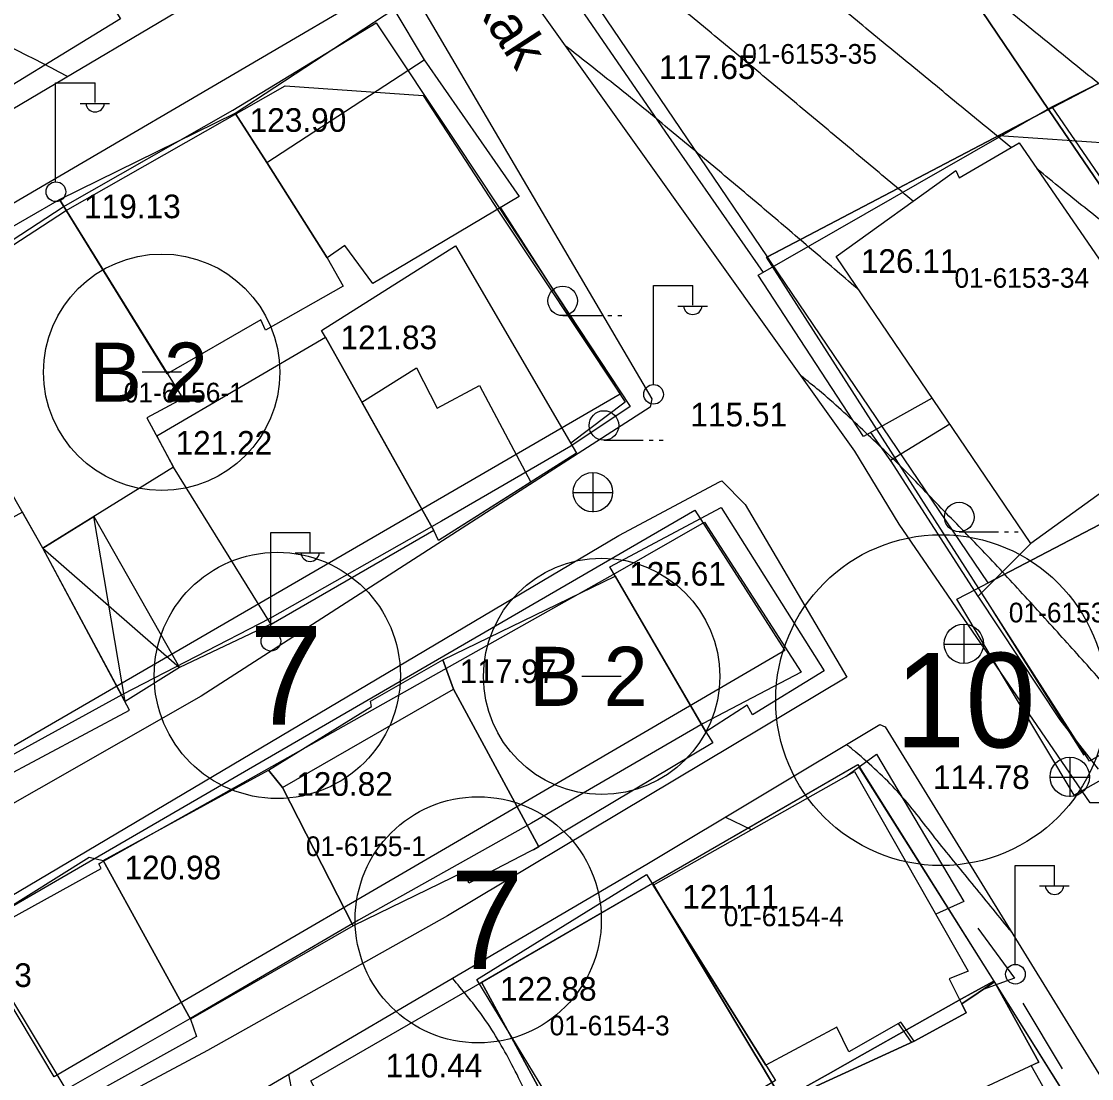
# Model space of a CAD drawing. Extents: x 412225 to 413380, y 4456471 to 4457189.
# Drawn here: x 413052.1 to 413106.4, y 4456895.9 to 4456949.5 of the extents above; entities that cross this region are included whole.
import ezdxf

# ---------------------------------------------------------------- set-up
doc = ezdxf.new("R2010")
doc.units = 0
for name, color, linetype in [('0_HALİHAZIR', 7, 'Continuous'), ('0_KADASTRO', 7, 'Continuous'), ('Level 27', 7, 'Continuous'), ('Level 28', 7, 'Continuous'), ('Level 32', 7, 'Continuous'), ('Level 58', 7, 'Continuous')]:
    doc.layers.add(name, color=color, linetype=linetype)

msp = doc.modelspace()

# ---------------------------------------------------------------- linework, layer by layer
at = {"layer": '0_HALİHAZIR'}
for p, q in [((413053.795, 4456941.409), (413053.795, 4456946.409)), ((413053.795, 4456946.409), (413055.795, 4456946.409)), ((413055.795, 4456945.409), (413055.795, 4456946.409)), ((413055.035, 4456945.369), (413056.535, 4456945.369)), ((413084.144, 4456931.12), (413084.144, 4456936.12)), ((413084.144, 4456936.12), (413086.144, 4456936.12)), ((413086.144, 4456935.12), (413086.144, 4456936.12)), ((413085.384, 4456935.08), (413086.884, 4456935.08)), ((413079.539, 4456934.591), (413081.539, 4456934.591)), ((413081.839, 4456934.591), (413082.039, 4456934.591)), ((413082.339, 4456934.591), (413082.539, 4456934.591)), ((413081.633, 4456928.267), (413083.633, 4456928.267)), ((413083.933, 4456928.267), (413084.133, 4456928.267)), ((413084.433, 4456928.267), (413084.633, 4456928.267)), ((413081.091, 4456924.616), (413081.091, 4456926.616)), ((413080.071, 4456925.606), (413082.071, 4456925.606)), ((413057.316, 4456915), (413055.727, 4456924.386)), ((413064.713, 4456918.588), (413064.713, 4456923.588)), ((413064.713, 4456923.588), (413066.713, 4456923.588)), ((413066.713, 4456922.588), (413066.713, 4456923.588)), ((413099.675, 4456923.617), (413101.675, 4456923.617)), ((413101.975, 4456923.617), (413102.175, 4456923.617)), ((413102.475, 4456923.617), (413102.675, 4456923.617)), ((413053.148, 4456922.783), (413060.081, 4456916.736)), ((413065.953, 4456922.548), (413067.453, 4456922.548)), ((413099.923, 4456916.926), (413099.923, 4456918.926)), ((413098.903, 4456917.916), (413100.903, 4456917.916)), ((413105.302, 4456910.168), (413105.302, 4456912.168)), ((413104.282, 4456911.158), (413106.282, 4456911.158)), ((413089.122, 4456908.489), (413087.793, 4456909.13)), ((413102.517, 4456901.681), (413102.517, 4456906.681)), ((413102.517, 4456906.681), (413104.517, 4456906.681)), ((413104.517, 4456905.681), (413104.517, 4456906.681)), ((413103.757, 4456905.641), (413105.257, 4456905.641)), ((413097.243, 4456897.7), (413096.595, 4456898.655)), ((413065.816, 4456895.094), (413065.63, 4456896.077))]:
    msp.add_line(p, q, dxfattribs=at)
for points in [[(413094.379, 4456927.708), (413075.671, 4456953.933), (413064.687, 4456969.316), (413063.953, 4456970.572), (413063.532, 4456971.572), (413063.534, 4456972.199), (413090.66, 4456987.803), (413092.085, 4456988.524), (413092.872, 4456988.675), (413093.96, 4456988.286), (413107.059, 4456970.576), (413119.482, 4456953.85), (413136.58, 4456931.951), (413137.309, 4456930.567), (413137.376, 4456930.194), (413137.355, 4456929.754), (413137.209, 4456929.362), (413109.964, 4456911.271), (413107.694, 4456910.075), (413106.974, 4456909.85), (413106.322, 4456909.85), (413096.628, 4456924.009)], [(413034.051, 4456935.027), (413027.482, 4456931.481), (413025.62, 4456931.591), (413025.037, 4456931.931), (413024.011, 4456932.834), (413018.904, 4456939.318), (413017.808, 4456941.453), (413017.249, 4456942.893), (413017.398, 4456943.916), (413049.751, 4456964.724), (413058.115, 4456969.735), (413059.157, 4456969.461), (413061.216, 4456967.512), (413067.043, 4456957.265), (413067.623, 4456955.982), (413067.576, 4456955.298), (413066.85, 4456954.114), (413046.371, 4456941.982)], [(413046.475, 4456937.288), (413071.112, 4456951.727), (413071.512, 4456951.752), (413084.063, 4456930.361), (413083.986, 4456929.949), (413061.177, 4456915.274), (413040.619, 4456903.545), (413040.417, 4456903.511), (413040.247, 4456903.518), (413027.41, 4456926.681), (413031.903, 4456929.13)], [(413062.914, 4456944.876), (413070.964, 4456950.147), (413072.511, 4456947.587), (413077.337, 4456940.637), (413069.893, 4456936.217), (413068.475, 4456938.153), (413067.581, 4456937.534), (413064.523, 4456942.363)], [(413072.511, 4456947.587), (413077.337, 4456940.637), (413069.893, 4456936.217), (413068.475, 4456938.153), (413067.581, 4456937.534), (413064.523, 4456942.363)], [(413053.992, 4456940.491), (413062.914, 4456944.876), (413064.523, 4456942.363), (413067.581, 4456937.534), (413068.386, 4456936.084), (413064.455, 4456933.863), (413064.211, 4456934.372), (413059.462, 4456931.646)], [(413102.719, 4456943.358), (413112.258, 4456929.48), (413103.305, 4456923.031), (413093.433, 4456937.6), (413099.503, 4456941.968), (413099.664, 4456941.593)], [(413053.992, 4456940.491), (413060.246, 4456930.378), (413058.431, 4456929.411), (413059.772, 4456926.9), (413053.148, 4456922.783), (413045.758, 4456935.756)], [(413067.49, 4456933.493), (413067.298, 4456933.841), (413074.1, 4456938.129), (413080.245, 4456927.603), (413073.238, 4456923.174), (413072.994, 4456923.683)], [(413058.926, 4456928.484), (413067.49, 4456933.493), (413072.994, 4456923.683), (413064.729, 4456918.91), (413059.772, 4456926.9)], [(413069.334, 4456930.206), (413072.125, 4456931.944), (413073.167, 4456929.896), (413075.308, 4456931.051), (413077.919, 4456926.133), (413073.238, 4456923.174), (413072.994, 4456923.683)], [(413061.501, 4456897.277), (413049.673, 4456890.969), (413049.199, 4456891.189), (413048.081, 4456891.953), (413044.111, 4456900.73), (413082.397, 4456923.435), (413087.5, 4456926.16), (413087.617, 4456926.212), (413088.813, 4456925.002), (413093.967, 4456916.245), (413073.697, 4456904.126)], [(413052.108, 4456924.608), (413043.1, 4456919.678), (413048.652, 4456909.825), (413057.551, 4456914.56), (413053.148, 4456922.783)], [(413081.93, 4456921.836), (413087.584, 4456924.859), (413092.818, 4456916.561), (413089.177, 4456914.318), (413088.902, 4456914.808), (413086.802, 4456913.455)], [(413060.081, 4456916.736), (413057.316, 4456915), (413053.148, 4456922.783), (413055.727, 4456924.386)], [(413073.455, 4456917.123), (413082.202, 4456921.368), (413086.802, 4456913.455), (413087.155, 4456912.909), (413078.058, 4456907.478), (413078.33, 4456907.618), (413073.989, 4456915.633)], [(413064.6, 4456911.519), (413069.825, 4456914.741), (413069.778, 4456915.013), (413073.455, 4456917.123), (413073.989, 4456915.633), (413078.33, 4456907.618), (413074.775, 4456905.783), (413074.564, 4456906.372), (413068.896, 4456903.604), (413065.313, 4456910.641)], [(413065.313, 4456910.641), (413073.989, 4456915.633), (413078.33, 4456907.618), (413074.775, 4456905.783), (413074.564, 4456906.372), (413068.896, 4456903.604)], [(413064.6, 4456911.519), (413065.313, 4456910.641), (413068.896, 4456903.604), (413060.638, 4456898.871), (413056.207, 4456906.925)], [(413084.135, 4456905.669), (413094.362, 4456911.452), (413100.132, 4456901.305), (413099.169, 4456900.917), (413100.032, 4456899.194), (413097.379, 4456897.762), (413096.708, 4456898.719), (413094.061, 4456897.207), (413093.455, 4456898.461), (413089.849, 4456896.544)], [(413055.49, 4456907.096), (413056.207, 4456906.925), (413060.638, 4456898.871), (413060.954, 4456897.991), (413051.011, 4456892.474), (413046.106, 4456901.226)], [(413083.792, 4456906.216), (413090.342, 4456895.756), (413081.511, 4456890.47), (413075.186, 4456900.881)], [(413091.073, 4456893.238), (413092.655, 4456894.088), (413092.046, 4456895.302), (413097.379, 4456897.762), (413100.032, 4456899.194), (413099.805, 4456899.647), (413101.459, 4456900.763), (413103.711, 4456896.694), (413099.613, 4456894.776), (413103.402, 4456887.718), (413096.406, 4456883.81)], [(413107.102, 4456889.833), (413103.332, 4456896.517), (413103.711, 4456896.694), (413101.459, 4456900.763), (413099.805, 4456899.647), (413100.032, 4456899.194), (413097.379, 4456897.762), (413092.046, 4456895.302), (413092.655, 4456894.088), (413091.073, 4456893.238), (413096.406, 4456883.81), (413103.402, 4456887.718)]]:
    msp.add_lwpolyline(points, close=True, dxfattribs=at)
for points in [[(413119.137, 4456952.411), (413099.599, 4456977.756), (413093.108, 4456986.076), (413092.219, 4456986.115), (413066.169, 4456970.946), (413084.909, 4456943.691), (413089.72, 4456936.788)], [(413104.369, 4456945.197), (413118.991, 4456952.591), (413128.787, 4456940.494)], [(413098.308, 4456930.405), (413094.815, 4456928.455), (413089.471, 4456936.645), (413104.368, 4456945.198), (413112.597, 4456933.212)], [(413076.379, 4456940.069), (413082.71, 4456930.197), (413079.946, 4456928.115)], [(413100.658, 4456920.311), (413096.182, 4456927.252), (413099.192, 4456929.102)], [(413096.281, 4456927.098), (413095.179, 4456928.658)], [(413104.796, 4456914.076), (413100.637, 4456920.342), (413103.305, 4456923.031)], [(413064.979, 4456919.054), (413060.081, 4456916.736)], [(413170.907, 4456685.636), (413151.928, 4456673.349), (413150.868, 4456674.019), (413150.219, 4456675.001), (413136.017, 4456715.95), (413125.491, 4456740.783), (413109.903, 4456772.28), (413097.267, 4456796.943), (413085.886, 4456823.793), (413072.678, 4456856.704), (413071.71, 4456858.426), (413060.306, 4456880.914), (413056.168, 4456890.292), (413056.179, 4456890.533), (413083.818, 4456906.745), (413095.637, 4456913.835), (413095.915, 4456913.724), (413109.286, 4456891.996), (413110.948, 4456888.736), (413111.525, 4456887.443)], [(413106.752, 4456911.561), (413104.796, 4456914.076)], [(413093.915, 4456911.2), (413095.474, 4456912.332), (413099.909, 4456904.851), (413098.485, 4456904.202)], [(413100.623, 4456903.5), (413102.474, 4456900.95), (413100.89, 4456900.379)], [(413102.899, 4456899.682), (413104.902, 4456896.346)]]:
    msp.add_lwpolyline(points, dxfattribs=at)
for centre, radius in [((413053.805, 4456940.884), 0.5), ((413079.539, 4456935.341), 0.75), ((413084.155, 4456930.596), 0.5), ((413081.633, 4456929.017), 0.75), ((413081.075, 4456925.624), 1), ((413099.675, 4456924.367), 0.75), ((413099.908, 4456917.934), 1), ((413064.723, 4456918.063), 0.5), ((413105.286, 4456911.176), 1), ((413102.528, 4456901.157), 0.5)]:
    msp.add_circle(centre, radius, dxfattribs=at)
for centre in [(413055.795, 4456945.412), (413086.144, 4456935.124), (413066.713, 4456922.591), (413104.517, 4456905.685)]:
    msp.add_arc(centre, 0.474, 184.8384, 355.1464, dxfattribs=at)
for points in [[(413114.406, 4456947.085), (413112.053, 4456948.945), (413109.704, 4456950.812), (413107.361, 4456952.685), (413105.021, 4456954.563), (413102.682, 4456956.441), (413100.341, 4456958.318), (413097.997, 4456960.19), (413095.645, 4456962.052), (413093.277, 4456963.894), (413090.887, 4456965.706), (413088.461, 4456967.47), (413086.001, 4456969.186), (413083.513, 4456970.863), (413081.015, 4456972.523), (413078.517, 4456974.185), (413076.026, 4456975.856), (413073.732, 4456977.748), (413073.532, 4456977.95)], [(413109.896, 4456943.824), (413107.565, 4456945.713), (413105.235, 4456947.602), (413102.905, 4456949.492), (413100.575, 4456951.381), (413098.245, 4456953.271), (413095.915, 4456955.161), (413093.585, 4456957.052), (413091.256, 4456958.942), (413088.926, 4456960.832), (413086.595, 4456962.721), (413084.249, 4456964.59), (413081.851, 4456966.388), (413079.37, 4456968.067), (413076.817, 4456969.64), (413074.258, 4456971.203), (413071.79, 4456972.895), (413069.615, 4456974.901), (413069.163, 4456975.437)], [(413102.312, 4456943.123), (413099.994, 4456945.028), (413097.677, 4456946.933), (413095.359, 4456948.838), (413093.042, 4456950.743), (413090.725, 4456952.648), (413088.406, 4456954.552), (413086.084, 4456956.452), (413083.759, 4456958.348), (413081.431, 4456960.24), (413079.096, 4456962.123), (413076.748, 4456963.991), (413074.379, 4456965.831), (413071.978, 4456967.629), (413069.539, 4456969.374), (413067.062, 4456971.067), (413064.962, 4456973.02)], [(413097.33, 4456940.404), (413095.032, 4456942.333), (413092.731, 4456944.258), (413090.426, 4456946.177), (413088.115, 4456948.09), (413085.799, 4456949.997), (413083.48, 4456951.9), (413081.159, 4456953.801), (413078.837, 4456955.701), (413076.513, 4456957.599), (413074.189, 4456959.495), (413071.864, 4456961.391), (413069.543, 4456963.291), (413068.206, 4456964.388)], [(413054.398, 4456946.737), (413047.555, 4456949.885), (413037.679, 4456953.544), (413035.88, 4456955.529), (413035.8, 4456955.751)], [(413094.613, 4456935.859), (413092.337, 4456937.814), (413090.056, 4456939.762), (413087.764, 4456941.698), (413085.461, 4456943.62), (413083.147, 4456945.53), (413080.805, 4456947.404), (413079.718, 4456948.259)], [(413119.152, 4456930.052), (413116.75, 4456931.849), (413114.351, 4456933.651), (413111.96, 4456935.462), (413109.578, 4456937.286), (413107.219, 4456939.139), (413104.88, 4456941.017), (413103.617, 4456942.051)], [(413107.162, 4456915.74), (413105.16, 4456917.974), (413103.145, 4456920.196), (413101.108, 4456922.399), (413099.023, 4456924.554), (413096.937, 4456926.705), (413094.782, 4456928.788), (413092.557, 4456930.788), (413091.662, 4456931.517)], [(413102.333, 4456903.295), (413102.225, 4456903.429), (413100.335, 4456905.759), (413098.443, 4456908.087), (413096.551, 4456910.415), (413094.409, 4456912.441), (413093.948, 4456912.822)], [(413085.733, 4456824.175), (413086.057, 4456827.148), (413086.383, 4456830.13), (413086.721, 4456833.111), (413087.065, 4456836.091), (413087.415, 4456839.071), (413087.765, 4456842.05), (413088.114, 4456845.03), (413088.458, 4456848.01), (413088.793, 4456850.991), (413089.116, 4456853.974), (413089.378, 4456856.961), (413089.286, 4456859.906), (413088.88, 4456862.85), (413088.184, 4456865.768), (413087.501, 4456868.689), (413086.825, 4456871.612), (413086.145, 4456874.534), (413085.453, 4456877.453), (413084.559, 4456880.303), (413083.478, 4456883.054), (413082.178, 4456885.757), (413080.866, 4456888.455), (413079.571, 4456891.162), (413078.282, 4456893.871), (413076.961, 4456896.563), (413075.413, 4456899.108), (413073.943, 4456900.953)]]:
    msp.add_spline(points, degree=3, dxfattribs=at)
at = {"layer": '0_KADASTRO'}
for points in [[(413092.998, 4456961.625), (413107.165, 4456969.043), (413118.39, 4456952.487), (413104.472, 4456945.2), (413104.204, 4456945.059)], [(413078.721, 4456954.148), (413092.998, 4456961.625), (413104.204, 4456945.059), (413089.935, 4456937.583)], [(413041.931, 4456954.66), (413050.317, 4456960.106), (413050.393, 4456959.988), (413057.092, 4456949.666), (413048.558, 4456944.442), (413042.164, 4456954.301)], [(413104.204, 4456945.059), (413104.472, 4456945.2), (413118.39, 4456952.487), (413118.471, 4456952.367), (413129.436, 4456936.196), (413129.616, 4456935.931), (413123.871, 4456932.924), (413123.468, 4456932.713), (413115.832, 4456928.717), (413115.475, 4456928.53)], [(413034.498, 4456928.23), (413037.373, 4456929.877), (413045.995, 4456934.79), (413054.176, 4456940.109), (413062.798, 4456945.031), (413070.075, 4456949.453), (413074.11, 4456943.386), (413076.253, 4456940.163), (413082.958, 4456929.98), (413079.945, 4456927.959), (413073.393, 4456924.15), (413064.666, 4456919.21), (413057.188, 4456915.358), (413048.266, 4456910.458), (413045.891, 4456909.107), (413040.212, 4456918.639)], [(413089.935, 4456937.583), (413104.204, 4456945.059), (413115.475, 4456928.53), (413107.52, 4456924.366), (413101.135, 4456921.024), (413090.131, 4456937.293)], [(413049.692, 4456902.987), (413056.103, 4456906.52), (413055.995, 4456906.761), (413056.073, 4456906.805), (413064.382, 4456911.478), (413064.771, 4456911.697), (413073.52, 4456916.62), (413082.227, 4456921.517), (413086.746, 4456924.106), (413091.64, 4456916.494), (413086.664, 4456913.881), (413077.954, 4456908.829), (413069.165, 4456903.892), (413060.616, 4456898.886), (413054.327, 4456895.295)], [(413099.546, 4456920.192), (413100.528, 4456920.706), (413101.135, 4456921.024), (413107.52, 4456924.366), (413107.891, 4456923.75), (413113.373, 4456914.659), (413105.518, 4456910.238)], [(413084.102, 4456905.773), (413088.263, 4456908.18), (413094.523, 4456911.803), (413101.427, 4456900.8), (413100.285, 4456900.177), (413099.797, 4456899.902), (413094.753, 4456897.06), (413093.014, 4456896.08), (413090.689, 4456894.771), (413089.612, 4456896.57), (413089.295, 4456897.1), (413084.592, 4456904.955)], [(413075.421, 4456900.749), (413084.102, 4456905.773), (413084.592, 4456904.955), (413089.295, 4456897.1), (413089.612, 4456896.57), (413090.689, 4456894.771), (413088.554, 4456893.45), (413081.683, 4456889.199), (413075.863, 4456899.934)], [(413066.757, 4456895.735), (413075.354, 4456900.71), (413075.421, 4456900.749), (413075.863, 4456899.934), (413081.683, 4456889.199), (413077.763, 4456886.774), (413073.119, 4456883.901), (413071.653, 4456886.629)], [(413088.554, 4456893.45), (413090.689, 4456894.771), (413093.014, 4456896.08), (413094.753, 4456897.06), (413099.797, 4456899.902), (413100.285, 4456900.177), (413101.427, 4456900.8), (413107.197, 4456891.594), (413107.483, 4456891.151), (413107.874, 4456890.527), (413109.814, 4456887.433), (413109.576, 4456887.293), (413096.14, 4456879.388)]]:
    msp.add_lwpolyline(points, close=True, dxfattribs=at)
at = {"layer": 'Level 27'}
for p, q in [((413143.876, 4456933.182), (413106.281, 4456911.978)), ((413082.45, 4456930.605), (413045.726, 4456909.294)), ((413049.325, 4456903.289), (413086.245, 4456924.714))]:
    msp.add_line(p, q, dxfattribs=at)
at = {"layer": 'Level 28'}
for p, q in [((413054.29, 4456939.92), (413065.447, 4456946.256)), ((413065.447, 4456946.256), (413072.458, 4456945.769)), ((413072.458, 4456945.769), (413076.282, 4456939.895)), ((413089.892, 4456937.56), (413101.683, 4456943.738)), ((413101.683, 4456943.738), (413139.383, 4456941.118)), ((413046.104, 4456934.583), (413054.29, 4456939.92)), ((413076.282, 4456939.895), (413082.45, 4456930.605)), ((413106.281, 4456911.978), (413089.892, 4456937.56)), ((413086.245, 4456924.714), (413090.813, 4456917.584)), ((413106.023, 4456912.273), (413101.387, 4456919.618)), ((413090.813, 4456917.584), (413080.32, 4456911.461)), ((413084.102, 4456905.773), (413094.523, 4456911.803)), ((413094.575, 4456911.674), (413101.427, 4456900.8)), ((413080.32, 4456911.461), (413071.651, 4456906.412)), ((413071.651, 4456906.412), (413063.34, 4456901.563)), ((413075.354, 4456900.71), (413084.102, 4456905.773)), ((413053.722, 4456895.951), (413049.325, 4456903.289)), ((413063.34, 4456901.563), (413053.722, 4456895.951)), ((413066.757, 4456895.735), (413075.354, 4456900.71)), ((413101.427, 4456900.8), (413107.197, 4456891.594))]:
    msp.add_line(p, q, dxfattribs=at)
at = {"layer": 'Level 32'}
for p, q in [((413060.179, 4456931.719), (413058.179, 4456931.719)), ((413082.515, 4456916.277), (413080.515, 4456916.277))]:
    msp.add_line(p, q, dxfattribs=at)
for centre in [(413059.18, 4456931.719), (413081.515, 4456916.277)]:
    msp.add_circle(centre, 6, dxfattribs=at)
at = {"layer": 'Level 58'}
for centre, radius in [((413098.755, 4456915.072), 8.4), ((413065.049, 4456916.326), 6.25), ((413075.251, 4456903.918), 6.25)]:
    msp.add_circle(centre, radius, dxfattribs=at)

# ---------------------------------------------------------------- texts
at = {"layer": '0_HALİHAZIR'}
msp.add_text('Burgaz  Sokak', height=2, rotation=302.9567, dxfattribs=at).set_placement((413067.745, 4456961.556))
for s, p in [('117.65', (413084.422, 4456946.606)), ('123.90', (413063.644, 4456943.924)), ('119.13', (413055.236, 4456939.538)), ('126.11', (413094.678, 4456936.765)), ('121.83', (413068.256, 4456932.888)), ('115.51 ', (413086.025, 4456928.968)), ('121.22', (413059.883, 4456927.532)), ('125.61', (413082.915, 4456920.884)), ('117.97', (413074.313, 4456915.936)), ('114.78 ', (413098.343, 4456910.558)), ('120.82', (413066.008, 4456910.214)), ('120.98', (413057.29, 4456905.972)), ('121.11', (413085.611, 4456904.482)), ('119.53', (413047.679, 4456900.509)), ('122.88', (413076.355, 4456899.812)), ('110.44 ', (413070.552, 4456895.918))]:
    msp.add_text(s, height=1.2, dxfattribs=at).set_placement(p)
at = {"layer": '0_KADASTRO'}
for s, p in [('01-6153-35', (413088.656, 4456947.381)), ('01-6153-35', (413088.656, 4456947.381)), ('01-6153-34', (413099.431, 4456936.007)), ('01-6153-34', (413099.431, 4456936.007)), ('01-6156-1', (413057.251, 4456930.185)), ('01-6156-1', (413057.251, 4456930.185)), ('01-6153-33', (413102.19, 4456919.018)), ('01-6153-33', (413102.19, 4456919.018)), ('01-6155-1', (413066.497, 4456907.155)), ('01-6155-1', (413066.497, 4456907.155)), ('01-6154-4', (413087.715, 4456903.592)), ('01-6154-4', (413087.715, 4456903.592)), ('01-6154-3', (413078.875, 4456898.052)), ('01-6154-3', (413078.875, 4456898.052))]:
    msp.add_text(s, height=1, dxfattribs=at).set_placement(p)
at = {"layer": 'Level 32'}
for p in [(413055.497, 4456930.221), (413077.833, 4456914.779)]:
    msp.add_text('B 2', height=3, dxfattribs=at).set_placement(p)
at = {"layer": 'Level 58'}
for s, height, p in [('7', 5, (413063.631, 4456913.827)), ('10', 4.8, (413096.413, 4456912.672)), ('7', 5, (413073.833, 4456901.418))]:
    msp.add_text(s, height=height, dxfattribs=at).set_placement(p)

doc.saveas('drawing.dxf')
